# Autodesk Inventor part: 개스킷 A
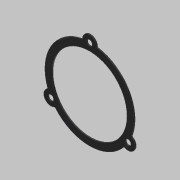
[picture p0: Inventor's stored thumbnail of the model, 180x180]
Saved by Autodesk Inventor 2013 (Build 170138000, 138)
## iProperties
Created: 2020-03
Part Number: 개스킷 A
Material: 고무
Document SubType Name: Modeling
Designer: mduedu
Density: 1 g/cm^3
Author: mduedu
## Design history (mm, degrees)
sketch "스케치1" dims "d1" = 88
  geometry: C1 r 37 at (0, 0); C2 r 7 at (0, 44); C3 r 7 at (-38.105, -22); C4 r 7 at (38.105, -22); 2 further points
  constraints: 4 centre point, 2 coincident, 2 vertical alignment, 9 other
  dimensions: "d0" = 74 diameter of C1; "d2" = 14 diameter of C2; "d5" = 360 deg dimension on point (0, 0) C2.centre (derived)
extrude "돌출1" new body sketch "스케치1" distance "d7" = 1; taper "d8" = 0 deg
fillet "모깎기1" dims "d9" = 1
sketch "스케치2"
  geometry: C1 r 37 at (0, 0) reference; A1 r 44 centre (0, 0) between (-7.817, 43.3) and (-41.408, -14.88) reference; A2 r 1 centre (-42.349, -15.218) between (-41.818, -16.066) and (-41.408, -14.88) reference; A3 r 7 centre (-38.105, -22) between (-41.818, -16.066) and (-34.823, -28.183) reference; A4 r 1 centre (-34.354, -29.066) between (-33.59, -28.42) and (-34.823, -28.183) reference; A5 r 44 centre (0, 0) between (-33.59, -28.42) and (33.59, -28.42) reference; A6 r 1 centre (34.354, -29.066) between (34.823, -28.183) and (33.59, -28.42) reference; A7 r 7 centre (38.105, -22) between (34.823, -28.183) and (41.818, -16.066) reference; A8 r 1 centre (42.349, -15.218) between (41.408, -14.88) and (41.818, -16.066) reference; A9 r 44 centre (0, 0) between (41.408, -14.88) and (7.817, 43.3) reference; A10 r 1 centre (7.995, 44.284) between (6.996, 44.249) and (7.817, 43.3) reference; A11 r 7 centre (0, 44) between (6.996, 44.249) and (-6.996, 44.249) reference; A12 r 1 centre (-7.995, 44.284) between (-7.817, 43.3) and (-6.996, 44.249) reference; 4 further points
  constraints: 3 coincident
hole "구멍1" sketch "스케치2" at (0, 44), (-38.105, -22), (38.105, -22) diameter "d10" = 5.5; stored, may be unused: countersink angle "d14" = 90 deg, drill point angle "d16" = 118 deg; dims "d11" = 6, "d12" = 10, "d13" = 5.7, "d15" = 8
node "솔리드1"
node "투영된 루프1"
